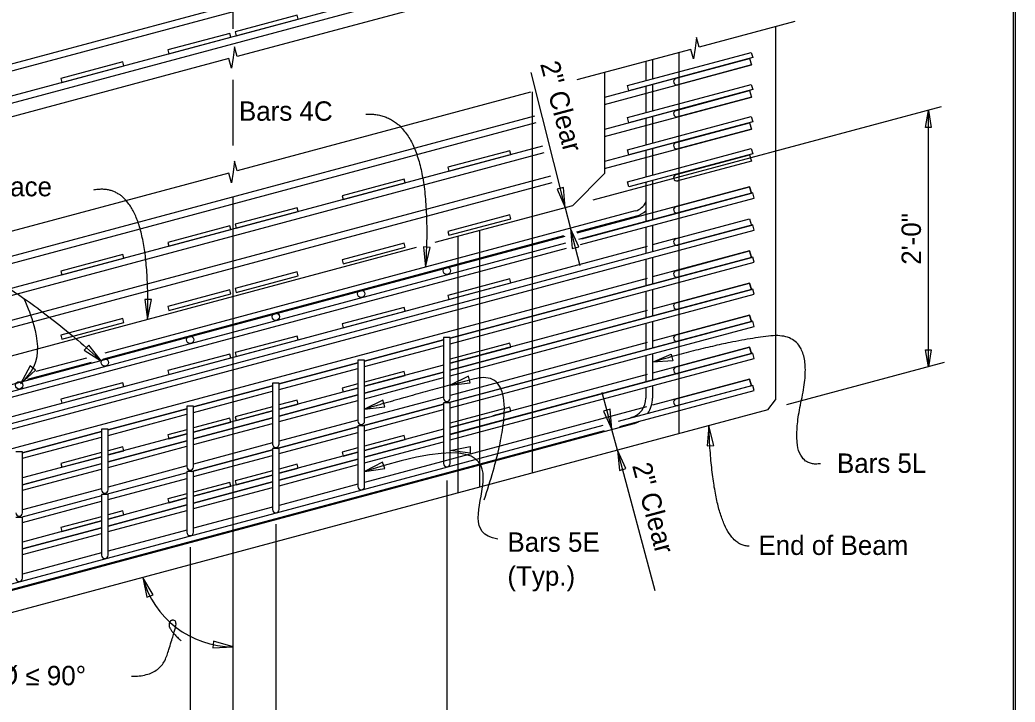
# Model space of a CAD drawing. Extents: x 0 to 30.8, y 0 to 19.8.
# Drawn here: x 23.04 to 30.8, y 4.26 to 9.58 of the extents above; entities that cross this region are included whole.
import ezdxf

# ---------------------------------------------------------------- set-up
doc = ezdxf.new("R2010")
doc.units = 0
for name, color, linetype in [('ActivePts-ConstElements', 7, 'Continuous'), ('BeamConc', 7, 'Continuous'), ('BeamConc_h', 7, 'Continuous'), ('CL_Major', 7, 'Continuous'), ('Dimension', 7, 'Continuous'), ('Miscellaneous', 7, 'Continuous'), ('Miscellaneous1', 7, 'Continuous'), ('Rebar', 7, 'Continuous'), ('Rebar_h', 7, 'Continuous'), ('TextStructures', 7, 'Continuous')]:
    doc.layers.add(name, color=color, linetype=linetype)

msp = doc.modelspace()

# ---------------------------------------------------------------- linework, layer by layer
at = {"layer": 'ActivePts-ConstElements'}
msp.add_lwpolyline([(0, 0), (30.7879, 0), (30.7879, 19.4596), (0, 19.4596)], close=True, dxfattribs=at)
at = {"layer": 'BeamConc'}
for p, q in [((28.9316, 9.5235), (28.9316, 6.6147)), ((27.5982, 9.1663), (27.5982, 8.3779)), ((27.5982, 8.3779), (27.3482, 8.1279)), ((27.3482, 8.1279), (26.2769, 7.8408)), ((26.1307, 7.8017), (22.0566, 6.71)), ((28.8712, 6.536), (28.9316, 6.6147)), ((28.8712, 6.536), (21.4512, 4.5478))]:
    msp.add_line(p, q, dxfattribs=at)
at = {"layer": 'BeamConc_h'}
for p, q in [((28.1816, 6.3512), (28.1816, 9.3226)), ((27.0357, 9.0157), (27.0357, 6.0442))]:
    msp.add_line(p, q, dxfattribs=at)
at = {"layer": 'CL_Major'}
for p, q in [((24.7024, 9.5072), (24.7024, 11.0727)), ((24.7024, 8.5974), (24.7024, 9.1088)), ((24.7024, 3.3009), (24.7024, 8.1933))]:
    msp.add_line(p, q, dxfattribs=at)
at = {"layer": 'Dimension'}
for p, q in [((27.2929, 8.1131), (27.0263, 9.1662)), ((30.224, 8.8985), (27.5072, 8.1705)), ((30.1238, 6.8716), (30.1238, 8.8716)), ((27.3325, 7.9569), (27.294, 8.1088)), ((27.3396, 8.1256), (27.3396, 8.1256)), ((27.4081, 7.658), (27.3338, 7.9515)), ((27.3827, 7.9646), (27.3827, 7.9646)), ((30.2473, 6.9047), (29.0185, 6.5754)), ((27.5789, 6.6753), (27.6571, 6.3832)), ((27.7003, 6.2222), (27.6571, 6.3832)), ((27.7302, 6.4028), (27.7302, 6.4028)), ((27.9938, 5.1267), (27.7003, 6.2222)), ((27.6272, 6.2026), (27.6272, 6.2026)), ((26.3691, 5.9871), (26.3691, 3.561)), ((25.0357, 5.6463), (25.0357, 3.561)), ((24.3691, 5.4666), (24.3691, 3.561))]:
    msp.add_line(p, q, dxfattribs=at)
for points in [[(26.8097, 9.8475), (24.7349, 9.2917), (24.7149, 9.3665), (24.7024, 9.283), (24.6897, 9.1993), (24.6697, 9.2742), (22.6484, 8.7328)], [(29.0828, 9.564), (28.3372, 9.3643), (28.3172, 9.4391), (28.3047, 9.3555), (28.2919, 9.2719), (28.2719, 9.3468), (27.3822, 9.1084)], [(27.0226, 9.0121), (24.7349, 8.3994), (24.7149, 8.4742), (24.7024, 8.3906), (24.6897, 8.307), (24.6697, 8.3819), (22.6484, 7.8405)]]:
    msp.add_lwpolyline(points, dxfattribs=at)
for points in [[(30.1238, 8.8714), (30.1459, 8.7377), (30.1017, 8.7377)], [(27.2929, 8.1131), (27.2802, 8.271), (27.2289, 8.258)], [(27.3338, 7.9515), (27.3465, 7.7936), (27.3978, 7.8065)], [(26.2036, 7.6485), (26.2395, 7.8028), (26.1867, 7.8061)], [(24.0361, 7.2404), (24.067, 7.3957), (24.0141, 7.3973)], [(23.6765, 6.9165), (23.5788, 7.0413), (23.5432, 7.0022)], [(30.1238, 6.8714), (30.1017, 7.0052), (30.1459, 7.0052)], [(27.9732, 6.9071), (28.1182, 6.971), (28.1312, 6.9197)], [(23.0462, 6.7395), (23.1623, 6.8472), (23.1204, 6.8794)], [(26.3951, 6.7289), (26.5524, 6.7481), (26.5373, 6.7988)], [(25.7285, 6.5417), (25.8857, 6.5609), (25.8706, 6.6117)], [(27.6571, 6.3832), (27.6423, 6.5409), (27.5912, 6.5272)], [(28.4125, 6.413), (28.3995, 6.2551), (28.4522, 6.2596)], [(26.3951, 6.2206), (26.5505, 6.2516), (26.552, 6.1987)], [(27.7003, 6.2222), (27.7151, 6.0645), (27.7663, 6.0782)], [(25.7285, 6.0559), (25.8853, 6.0785), (25.8691, 6.1289)], [(23.9984, 5.2302), (24.0296, 5.0754), (24.0794, 5.0946)], [(24.7024, 4.69), (24.5505, 4.7331), (24.5448, 4.6801)]]:
    msp.add_lwpolyline(points, close=True, dxfattribs=at)
msp.add_arc((24.7024, 5.4189), 0.7289, 195, 270, dxfattribs=at)
for points, degree in [([(25.7367, 8.8413), (26.278, 8.8696), (26.2036, 7.6486)], 2), ([(24.036, 7.2404), (24.0677, 8.3346), (23.6151, 8.2497)], 2), ([(21.7414, 7.8736), (22.5391, 7.9529), (23.6765, 6.9165)], 2), ([(29.2838, 6.1167), (29.0154, 6.0771), (29.2555, 7.1567), (28.5095, 7.0669), (27.9732, 6.9072)], 2), ([(26.6609, 5.834), (27.0095, 6.8858), (26.159, 6.67), (25.7284, 6.5418)], 2), ([(28.7267, 5.4738), (28.4462, 5.4738), (28.4124, 6.413)], 2), ([(26.7677, 5.5283), (26.5259, 5.5675), (26.7502, 5.9972), (26.5827, 6.3303), (25.7284, 6.056)], 3), ([(23.9099, 4.4599), (24.1325, 4.4575), (24.2377, 4.7766), (24.2685, 4.8967), (24.2035, 4.8967), (24.2035, 4.8217), (24.2975, 4.7366)], 2)]:
    msp.add_open_spline(points, degree=degree, dxfattribs=at)
msp.add_spline([(23.075, 7.3998), (23.1495, 7.1944), (23.1495, 6.8739), (23.0462, 6.7395)], degree=3, dxfattribs=at)
at = {"layer": 'Miscellaneous'}
for p, q in [((26.6232, 7.9336), (26.6232, 5.9336)), ((26.4565, 7.889), (26.4565, 5.889))]:
    msp.add_line(p, q, dxfattribs=at)
at = {"layer": 'Miscellaneous1'}
msp.add_lwpolyline([(0, 19.8), (30.8, 19.8), (30.8, 0), (0, 0)], close=True, dxfattribs=at)
at = {"layer": 'Rebar'}
for p, q in [((27.7773, 9.0644), (28.7433, 9.3232)), ((28.7433, 9.3232), (28.7541, 9.2829)), ((28.7541, 9.2829), (27.7881, 9.0241)), ((27.9212, 9.2528), (27.9212, 9.1029)), ((27.9732, 9.2668), (27.9732, 9.1169)), ((28.1565, 9.1214), (28.7302, 9.2752)), ((28.7302, 9.2752), (28.7437, 9.2248)), ((28.7437, 9.2248), (28.17, 9.0711)), ((27.7773, 8.8144), (28.7433, 9.0732)), ((27.7881, 9.0241), (27.7773, 9.0644)), ((28.7541, 9.0329), (27.7881, 8.7741)), ((27.9212, 9.0597), (27.9212, 8.8529)), ((27.9732, 9.0737), (27.9732, 8.8669)), ((28.1565, 8.8714), (28.7302, 9.0252)), ((28.7302, 9.0252), (28.7437, 8.9748)), ((28.7433, 9.0732), (28.7541, 9.0329)), ((28.7437, 8.9748), (28.17, 8.8211)), ((27.7773, 8.5644), (28.7433, 8.8232)), ((27.7881, 8.7741), (27.7773, 8.8144)), ((28.7541, 8.7829), (27.7881, 8.5241)), ((27.9212, 8.8097), (27.9212, 8.6029)), ((27.9732, 8.8237), (27.9732, 8.6169)), ((28.1565, 8.6214), (28.7302, 8.7752)), ((28.7302, 8.7752), (28.7437, 8.7248)), ((28.7433, 8.8232), (28.7541, 8.7829)), ((28.7437, 8.7248), (28.17, 8.5711)), ((27.7773, 8.3144), (28.7433, 8.5732)), ((27.7881, 8.5241), (27.7773, 8.5644)), ((27.9212, 8.5597), (27.9212, 8.3529)), ((27.9732, 8.5737), (27.9732, 8.3669)), ((28.7433, 8.5732), (28.7541, 8.5329)), ((28.7541, 8.5329), (27.7881, 8.2741)), ((28.1565, 8.3714), (28.7302, 8.5252)), ((28.7437, 8.4748), (28.17, 8.3211)), ((28.7302, 8.5252), (28.7437, 8.4748)), ((27.7881, 8.2741), (27.7773, 8.3144)), ((27.9212, 8.3097), (27.9212, 8.0044)), ((27.9732, 8.3237), (27.9732, 8.0184)), ((28.7541, 8.2276), (27.3964, 7.8638)), ((28.1565, 8.1214), (28.7302, 8.2752)), ((28.7437, 8.2248), (28.17, 8.0711)), ((28.7302, 8.2752), (28.7437, 8.2248)), ((28.7649, 8.1874), (28.7541, 8.2276)), ((27.4114, 7.8247), (28.7649, 8.1874)), ((27.8389, 8.0868), (23.7025, 6.9785)), ((27.384, 7.9232), (27.8497, 8.048)), ((28.1565, 7.8714), (28.7302, 8.0252)), ((28.7302, 8.0252), (28.7437, 7.9748)), ((28.7541, 7.9776), (20.6399, 5.8034)), ((20.6507, 5.7632), (28.7649, 7.9374)), ((27.9212, 7.9613), (27.9212, 7.7544)), ((27.9732, 7.9752), (27.9732, 7.7684)), ((28.7437, 7.9748), (28.17, 7.8211)), ((28.7649, 7.9374), (28.7541, 7.9776)), ((27.2958, 7.8369), (20.6399, 6.0534)), ((23.695, 6.9348), (27.2809, 7.8956)), ((20.6507, 6.0132), (27.3031, 7.7957)), ((28.1565, 7.6214), (28.7302, 7.7752)), ((28.7302, 7.7752), (28.7437, 7.7248)), ((28.7541, 7.7276), (26.3951, 7.0955)), ((26.3951, 7.0524), (28.7649, 7.6874)), ((27.9212, 7.7113), (27.9212, 7.5044)), ((27.9732, 7.7252), (27.9732, 7.5184)), ((28.7437, 7.7248), (28.17, 7.5711)), ((28.7649, 7.6874), (28.7541, 7.7276)), ((28.7541, 7.4776), (26.3951, 6.8455)), ((27.9212, 7.4613), (27.9212, 7.2544)), ((27.9732, 7.4752), (27.9732, 7.2684)), ((28.1565, 7.3714), (28.7302, 7.5252)), ((28.7437, 7.4748), (28.17, 7.3211)), ((28.7302, 7.5252), (28.7437, 7.4748)), ((28.7649, 7.4374), (28.7541, 7.4776)), ((26.3951, 6.8024), (28.7649, 7.4374)), ((28.7541, 7.2276), (26.3806, 6.5916)), ((27.9732, 7.2252), (27.9732, 7.0184)), ((28.1565, 7.1214), (28.7302, 7.2752)), ((28.7437, 7.2248), (28.17, 7.0711)), ((28.7302, 7.2752), (28.7437, 7.2248)), ((28.7649, 7.1874), (28.7541, 7.2276)), ((26.3951, 6.5524), (28.7649, 7.1874)), ((27.9212, 7.2113), (27.9212, 7.0044)), ((26.343, 7.0816), (25.7284, 6.9169)), ((26.343, 7.1016), (26.343, 6.6277)), ((26.3951, 7.1016), (26.343, 7.1016)), ((26.3951, 6.6277), (26.3951, 7.1016)), ((25.7284, 6.8737), (26.343, 7.0384)), ((28.1565, 6.8714), (28.7302, 7.0252)), ((28.7302, 7.0252), (28.7437, 6.9748)), ((23.1034, 6.7763), (23.5992, 6.9091)), ((23.5596, 6.9402), (23.1662, 6.8347)), ((25.6764, 6.923), (25.6764, 6.449)), ((25.7284, 6.923), (25.6764, 6.923)), ((25.7284, 6.449), (25.7284, 6.923)), ((26.3951, 6.3024), (28.7649, 6.9374)), ((28.7541, 6.9776), (26.3978, 6.3462)), ((27.9212, 6.9613), (27.9212, 6.7544)), ((27.9732, 6.9752), (27.9732, 6.7684)), ((28.7437, 6.9748), (28.17, 6.8211)), ((28.7649, 6.9374), (28.7541, 6.9776)), ((25.6764, 6.9029), (25.0618, 6.7383)), ((25.0618, 6.6951), (25.6764, 6.8598)), ((26.343, 6.8316), (25.7284, 6.6669)), ((25.7284, 6.6237), (26.343, 6.7884)), ((28.1565, 6.6214), (28.7302, 6.7752)), ((28.7302, 6.7752), (28.7437, 6.7248)), ((25.0097, 6.7243), (24.3951, 6.5596)), ((24.3951, 6.5165), (25.0097, 6.6812)), ((25.0097, 6.7443), (25.0097, 6.2703)), ((25.0618, 6.7443), (25.0097, 6.7443)), ((25.0618, 6.2703), (25.0618, 6.7443)), ((28.7541, 6.7276), (27.7063, 6.4468)), ((27.7173, 6.4067), (28.7649, 6.6874)), ((27.9211, 6.7113), (27.9211, 6.6278)), ((27.9732, 6.7252), (27.9732, 6.6278)), ((28.7437, 6.7248), (28.17, 6.5711)), ((28.7649, 6.6874), (28.7541, 6.7276)), ((25.6764, 6.6529), (25.0618, 6.4883)), ((25.0618, 6.4451), (25.6764, 6.6098)), ((24.343, 6.5457), (23.7284, 6.381)), ((24.343, 6.5657), (24.343, 6.0918)), ((24.3951, 6.5657), (24.343, 6.5657)), ((24.3951, 6.0918), (24.3951, 6.5657)), ((26.343, 6.5816), (25.7139, 6.413)), ((25.7284, 6.3737), (26.343, 6.5384)), ((26.343, 6.5916), (26.343, 6.1177)), ((26.3951, 6.5916), (26.343, 6.5916)), ((26.3951, 6.1177), (26.3951, 6.5916)), ((23.7284, 6.3378), (24.343, 6.5025)), ((25.0097, 6.4743), (24.3951, 6.3096)), ((27.5855, 6.4145), (20.6399, 4.5534)), ((20.6507, 4.5132), (27.598, 6.3747)), ((21.6938, 4.7854), (27.8189, 6.4266)), ((23.6764, 6.367), (23.0618, 6.2024)), ((23.6764, 6.3871), (23.6764, 5.9131)), ((23.7284, 6.3871), (23.6764, 6.3871)), ((23.7284, 5.9131), (23.7284, 6.3871)), ((24.3951, 6.2665), (25.0097, 6.4312)), ((25.6764, 6.4029), (25.047, 6.2343)), ((25.6764, 6.413), (25.6764, 5.939)), ((25.7284, 6.413), (25.6764, 6.413)), ((25.7284, 5.939), (25.7284, 6.413)), ((23.0618, 6.1592), (23.6764, 6.3239)), ((24.343, 6.2957), (23.7284, 6.131)), ((25.0618, 6.1951), (25.6764, 6.3598)), ((26.343, 6.3316), (25.7284, 6.1669)), ((25.7284, 6.1237), (26.343, 6.2884)), ((23.0618, 6.2084), (23.0097, 6.2084)), ((23.0618, 5.7344), (23.0618, 6.2084)), ((23.7284, 6.0878), (24.343, 6.2525)), ((25.0097, 6.2243), (24.3806, 6.0557)), ((25.0097, 6.2343), (25.0097, 5.7603)), ((25.0618, 6.2343), (25.0097, 6.2343)), ((25.0618, 5.7603), (25.0618, 6.2343)), ((24.3951, 6.0165), (25.0097, 6.1812)), ((25.6764, 6.1529), (25.0618, 5.9883)), ((23.6764, 6.117), (23.0618, 5.9524)), ((23.0618, 5.9092), (23.6764, 6.0739)), ((24.343, 6.0557), (24.343, 5.5818)), ((24.3951, 6.0557), (24.343, 6.0557)), ((24.3951, 5.5818), (24.3951, 6.0557)), ((25.0618, 5.9451), (25.6764, 6.1098)), ((24.343, 6.0457), (23.7139, 5.8771)), ((23.7284, 5.8378), (24.343, 6.0025)), ((25.0097, 5.9743), (24.3951, 5.8096)), ((24.3951, 5.7665), (25.0097, 5.9312)), ((23.6764, 5.867), (23.047, 5.6984)), ((23.0618, 5.6592), (23.6764, 5.8239)), ((23.6764, 5.8771), (23.6764, 5.4031)), ((23.7284, 5.8771), (23.6764, 5.8771)), ((23.7284, 5.4031), (23.7284, 5.8771)), ((24.343, 5.7957), (23.7284, 5.631)), ((23.7284, 5.5878), (24.343, 5.7525)), ((23.0618, 5.6984), (23.0097, 5.6984)), ((23.0618, 5.2244), (23.0618, 5.6984)), ((23.6764, 5.617), (23.0618, 5.4524)), ((23.0618, 5.4092), (23.6764, 5.5739))]:
    msp.add_line(p, q, dxfattribs=at)
for points in [[(24.7275, 9.4526), (25.2105, 9.582), (25.2024, 9.6122), (24.7194, 9.4828)], [(24.2024, 9.3119), (24.6854, 9.4413), (24.6773, 9.4715), (24.1943, 9.3421)], [(23.3691, 9.0886), (23.852, 9.218), (23.8439, 9.2482), (23.361, 9.1188)], [(26.3861, 8.397), (26.8691, 8.5264), (26.861, 8.5566), (26.378, 8.4272)], [(25.5609, 8.1759), (26.0438, 8.3053), (26.0357, 8.3355), (25.5528, 8.2061)], [(24.7275, 7.9526), (25.2105, 8.082), (25.2024, 8.1122), (24.7194, 7.9828)], [(26.3861, 7.897), (26.8691, 8.0264), (26.861, 8.0566), (26.378, 7.9272)], [(24.2024, 7.8119), (24.6854, 7.9413), (24.6773, 7.9715), (24.1943, 7.8421)], [(25.5609, 7.6759), (26.0438, 7.8053), (26.0357, 7.8355), (25.5528, 7.7061)], [(23.3691, 7.5886), (23.852, 7.718), (23.8439, 7.7482), (23.361, 7.6188)], [(24.7275, 7.4526), (25.2105, 7.582), (25.2024, 7.6122), (24.7194, 7.4828)], [(26.3861, 7.397), (26.8691, 7.5264), (26.861, 7.5566), (26.378, 7.4272)], [(24.2024, 7.3119), (24.6854, 7.4413), (24.6773, 7.4715), (24.1943, 7.3421)], [(25.5609, 7.1759), (26.0438, 7.3053), (26.0357, 7.3355), (25.5528, 7.2061)], [(23.3691, 7.0886), (23.852, 7.218), (23.8439, 7.2482), (23.361, 7.1188)], [(24.7275, 6.9526), (25.2105, 7.082), (25.2024, 7.1122), (24.7194, 6.9828)], [(24.2024, 6.8119), (24.6854, 6.9413), (24.6773, 6.9715), (24.1943, 6.8421)], [(23.3691, 6.5886), (23.852, 6.718), (23.8439, 6.7482), (23.361, 6.6188)]]:
    msp.add_lwpolyline(points, close=True, dxfattribs=at)
for points in [[(26.3951, 6.8456), (28.7437, 7.4749), (28.7302, 7.5251), (27.9732, 7.3223)], [(26.3951, 6.8994), (26.8691, 7.0264), (26.861, 7.0566), (26.3951, 6.9318)], [(25.7284, 6.7208), (26.0438, 6.8053), (26.0357, 6.8355), (25.7284, 6.7532)], [(25.6764, 6.7392), (25.5528, 6.7061), (25.5609, 6.6759), (25.6764, 6.7068)], [(25.0618, 6.5422), (25.2105, 6.582), (25.2024, 6.6122), (25.0618, 6.5745)], [(25.0097, 6.5606), (24.7194, 6.4828), (24.7275, 6.4526), (25.0097, 6.5282)], [(26.3951, 6.3994), (26.8691, 6.5264), (26.861, 6.5566), (26.3951, 6.4318)], [(24.3951, 6.3635), (24.6854, 6.4413), (24.6773, 6.4715), (24.3951, 6.3959)], [(24.343, 6.3819), (24.1943, 6.3421), (24.2024, 6.3119), (24.343, 6.3496)], [(25.7284, 6.2208), (26.0438, 6.3053), (26.0357, 6.3355), (25.7284, 6.2532)], [(23.7284, 6.1849), (23.852, 6.218), (23.8439, 6.2482), (23.7284, 6.2173)], [(25.6764, 6.2392), (25.5528, 6.2061), (25.5609, 6.1759), (25.6764, 6.2068)], [(23.6764, 6.2033), (23.361, 6.1188), (23.3691, 6.0886), (23.6764, 6.171)], [(25.0097, 6.0606), (24.7194, 5.9828), (24.7275, 5.9526), (25.0097, 6.0282)], [(25.0618, 6.0422), (25.2105, 6.082), (25.2024, 6.1122), (25.0618, 6.0745)], [(24.3951, 5.8635), (24.6854, 5.9413), (24.6773, 5.9715), (24.3951, 5.8959)], [(24.343, 5.8819), (24.1943, 5.8421), (24.2024, 5.8119), (24.343, 5.8496)], [(23.7284, 5.6849), (23.852, 5.718), (23.8439, 5.7482), (23.7284, 5.7173)], [(23.6764, 5.7033), (23.361, 5.6188), (23.3691, 5.5886), (23.6764, 5.671)]]:
    msp.add_lwpolyline(points, dxfattribs=at)
for centre in [(26.3691, 7.6201), (25.7024, 7.4414), (25.0357, 7.2627), (24.3691, 7.0827), (23.7024, 6.9052), (23.0357, 6.7274)]:
    msp.add_circle(centre, 0.0287, dxfattribs=at)
for centre, radius, start, end in [((28.1632, 9.0963), 0.026, 105, 285), ((28.1632, 8.8463), 0.026, 105, 285), ((28.1632, 8.5963), 0.026, 105, 285), ((28.1632, 8.3463), 0.026, 105, 285), ((27.8066, 8.2075), 0.125, 285, 336.44353), ((27.8065, 8.209), 0.1667, 285, 313.43746), ((28.1632, 8.0963), 0.026, 105, 285), ((28.1632, 7.8463), 0.026, 105, 285), ((28.1632, 7.5963), 0.026, 105, 285), ((28.1632, 7.3463), 0.026, 105, 285), ((28.1632, 7.0963), 0.026, 105, 285), ((28.1632, 6.8463), 0.026, 105, 285), ((26.3691, 6.6277), 0.026, 179.99982, 359.99949), ((27.7649, 6.6278), 0.1562, 285, 360), ((27.7649, 6.6278), 0.2083, 324.99028, 360), ((28.1632, 6.5963), 0.026, 105, 285), ((25.7024, 6.449), 0.026, 179.99982, 359.99949), ((27.7649, 6.6278), 0.2083, 285, 299.93885), ((25.0357, 6.2703), 0.026, 179.99982, 359.99949), ((24.3691, 6.0918), 0.026, 179.99982, 359.99949), ((26.3691, 6.1177), 0.026, 179.99982, 359.99949), ((23.7024, 5.9131), 0.026, 179.99982, 359.99949), ((25.7024, 5.939), 0.026, 179.99982, 359.99949), ((25.0357, 5.7603), 0.026, 179.99982, 359.99949), ((23.0357, 5.7344), 0.026, 179.99982, 359.99949), ((24.3691, 5.5818), 0.026, 179.99982, 359.99949), ((23.7024, 5.4031), 0.026, 179.99982, 359.99949), ((23.0357, 5.2244), 0.026, 179.99982, 359.99949)]:
    msp.add_arc(centre, radius, start, end, dxfattribs=at)
at = {"layer": 'Rebar_h'}
for p, q in [((28.7302, 9.2751), (27.5982, 8.9718)), ((27.5982, 8.918), (28.7437, 9.2249)), ((28.7302, 9.0251), (27.5982, 8.7218)), ((27.5982, 8.668), (28.7437, 8.9749)), ((21.2385, 7.2139), (27.0661, 8.7754)), ((27.0527, 8.8256), (21.6267, 7.3717)), ((28.7302, 8.7751), (27.5982, 8.4718)), ((27.5982, 8.418), (28.7437, 8.7249)), ((21.2385, 6.9639), (27.1286, 8.5421)), ((27.1152, 8.5924), (21.6267, 7.1217)), ((21.2385, 6.7139), (27.1911, 8.3089)), ((27.1777, 8.3591), (21.6267, 6.8717)), ((28.7302, 8.2751), (27.3843, 7.9145)), ((27.4223, 7.8708), (28.7437, 8.2249)), ((28.7437, 8.2249), (28.7302, 8.2751)), ((27.2888, 7.8889), (20.6513, 6.1104)), ((28.7302, 6.7751), (27.9732, 6.5723)), ((28.7437, 6.7249), (28.7302, 6.7751)), ((27.9267, 6.5598), (25.7284, 5.9708))]:
    msp.add_line(p, q, dxfattribs=at)
for points in [[(28.7302, 10.7751), (20.6513, 8.6104), (20.6648, 8.5601), (28.7437, 10.7249)], [(28.7302, 10.5251), (20.6513, 8.3604), (20.6648, 8.3101), (28.7437, 10.4749)]]:
    msp.add_lwpolyline(points, close=True, dxfattribs=at)
for points in [[(28.1553, 7.8711), (27.9732, 7.8223)], [(27.9316, 7.8111), (21.4733, 6.0806)], [(26.3951, 7.0956), (28.7437, 7.7249), (28.7302, 7.7751), (27.9732, 7.5723)], [(27.9316, 7.5611), (21.4733, 5.8306)], [(27.9316, 7.3111), (26.3951, 6.8994)], [(26.3951, 6.5956), (28.7437, 7.2249), (28.7302, 7.2751), (27.9732, 7.0723)], [(25.7284, 6.9169), (26.343, 7.0816)], [(27.9316, 7.0611), (26.3951, 6.6494)], [(26.3951, 6.3456), (28.7437, 6.9749), (28.7302, 7.0251), (27.9732, 6.8223)], [(25.0618, 6.7383), (25.6764, 6.903)], [(26.343, 6.8855), (25.7284, 6.7208)], [(25.7284, 6.6669), (26.343, 6.8316)], [(27.9316, 6.8111), (26.7284, 6.4888)], [(24.3951, 6.5597), (25.0097, 6.7244)], [(25.6764, 6.7068), (25.0618, 6.5422)], [(25.0618, 6.4883), (25.6764, 6.653)], [(26.343, 6.6355), (25.7284, 6.4708)], [(23.7284, 6.381), (24.343, 6.5457)], [(25.0097, 6.5282), (24.3951, 6.3635)], [(25.7137, 6.413), (26.343, 6.5816)], [(24.3951, 6.3097), (25.0097, 6.4744)], [(25.6764, 6.4568), (25.0618, 6.2922)], [(26.6764, 6.4748), (26.3951, 6.3994)], [(23.0618, 6.2024), (23.6764, 6.3671)], [(25.0468, 6.2343), (25.6764, 6.403)], [(26.343, 6.3855), (25.7284, 6.2208)], [(24.343, 6.3496), (23.7284, 6.1849)], [(23.7284, 6.131), (24.343, 6.2957)], [(25.7284, 6.1669), (26.343, 6.3316)], [(24.3803, 6.0557), (25.0097, 6.2244)], [(25.0097, 6.2782), (24.3951, 6.1135)], [(23.6764, 6.171), (23.0618, 6.0063)], [(25.6764, 6.2068), (25.0618, 6.0422)], [(25.0618, 5.9883), (25.6764, 6.153)], [(23.0618, 5.9524), (23.6764, 6.1171)], [(24.343, 6.0996), (23.7284, 5.9349)], [(25.0097, 6.0282), (24.3951, 5.8635)], [(23.6764, 5.921), (23.0618, 5.7563)], [(24.3951, 5.8097), (25.0097, 5.9744)], [(25.6764, 5.9568), (25.0618, 5.7922)], [(24.343, 5.8496), (23.7284, 5.6849)], [(23.7284, 5.631), (24.343, 5.7957)], [(25.0097, 5.7782), (24.3951, 5.6135)], [(23.6764, 5.671), (23.0618, 5.5063)], [(23.0618, 5.4524), (23.6764, 5.6171)], [(24.343, 5.5996), (23.7284, 5.4349)], [(23.6764, 5.421), (23.0618, 5.2563)]]:
    msp.add_lwpolyline(points, dxfattribs=at)

# ---------------------------------------------------------------- texts
at = {"layer": 'Dimension'}
for s, p in [('Bars 5E ', (26.8421, 5.4302)), ('(Typ.)', (26.8421, 5.1662))]:
    msp.add_text(s, height=0.1512, dxfattribs=at).set_placement(p)
at = {"layer": 'TextStructures'}
for s, rotation, p in [('2" Clear', 285, (27.0963, 9.2331)), ('2\'-0"', 90, (30.066, 7.6678)), ('2" Clear', 285, (27.8129, 6.1027))]:
    msp.add_text(s, height=0.1512, rotation=rotation, dxfattribs=at).set_placement(p)
for s, p in [('Bars 4C', (24.7488, 8.7902)), ('Void Face', (22.3808, 8.2013)), ('Bars 5L', (29.4112, 6.0453)), ('End of Beam', (28.7987, 5.4055)), ('75° ≤ Ø ≤ 90°', (22.3415, 4.3895))]:
    msp.add_text(s, height=0.1512, dxfattribs=at).set_placement(p)

doc.saveas('drawing.dxf')
